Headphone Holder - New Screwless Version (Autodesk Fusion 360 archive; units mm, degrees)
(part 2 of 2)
sketch "Sketch12" plane through (0, -10.6, 0) normal (0, 1, 0) x axis (-1, 0, 0)
  line L1 (27.8828, -27.5) -> (-27.8828, -27.5)
  line L2 (27.8828, 27.5) -> (27.8828, -27.5)
  line L3 (-27.8828, 27.5) -> (27.8828, 27.5)
  line L4 (-27.8828, -27.5) -> (-27.8828, 27.5)
  circle C1 centre (13.4, 0) radius 1.6
  circle C2 centre (-13.4, 0) radius 1.6
  circle C3 centre (13.4, 0) radius 1.25
  circle C4 centre (-13.4, 0) radius 1.25
  concentric C1 C3
  concentric C2 C4
  equal C3 C4
  dimension "d220" diameter C3 = 2.5
extrude "Extrude13" cut sketch "Sketch12" profile of C3 C4 against normal blind 2
copy_paste_bodies "CopyPasteBodies1"
copy_paste_bodies "CopyPasteBodies2"
copy_paste_bodies "CopyPasteBodies3"
delete_face "DeleteFace1"
delete_face "DeleteFace2"
split "Split1" bodies "Peg Left"
copy_paste_bodies "CopyPasteBodies1"
copy_paste_bodies "CopyPasteBodies3"
move "Move1"
combine "Combine1" bodies "Peg Left"
copy_paste_bodies "CutPasteBodies"
sketch "Sketch13" plane through (0, -10.2, 0) normal (0, -1, 0) x axis (1, 0, 0)
  line L1 (-17.4, -27.3) -> (-17.4, 27.3)
  line L2 (17.4, -27.3) -> (-17.4, -27.3)
  line L3 (17.4, 27.3) -> (17.4, -27.3)
  line L4 (-17.4, 27.3) -> (17.4, 27.3)
  line L5 (2.4, 0) -> (-2.4, 0)
  line L6 (-2.6, -7.7) -> (2.6, -7.7)
  line L7 (-2.6, 7.7) -> (-2.6, -7.7)
  line L8 (2.6, 7.7) -> (-2.6, 7.7)
  line L9 (2.6, -7.7) -> (2.6, 7.7)
  line L10 (-2.6, 7.7) -> (2.6, -7.7)
  line L11 (2.6, 7.7) -> (-2.6, -7.7)
  circle C1 centre (-13.4, 0) radius 1.6
  circle C2 centre (13.4, 0) radius 1.6
  arc A1 centre (0, -12.3) radius 2.4 clockwise from (2.4, -12.3) to (-2.4, -12.3)
  arc A2 centre (0, -12.3) radius 2.4 clockwise from (2.4, -12.3) to (-2.4, -12.3)
  arc A3 centre (0, -4.9) radius 2.4 clockwise from (2.4, -4.9) to (-2.4, -4.9)
  arc A4 centre (0, -4.9) radius 2.4 clockwise from (2.4, -4.9) to (-2.4, -4.9)
  point P20 (0, 0)
  point P1 (0, 0)
  point P16 (2.6, -7.7)
  point P17 (-2.6, -7.7)
  point P18 (-2.6, 7.7)
  horizontal L6
  perpendicular L6 L7
  parallel L6 L8
  parallel L7 L9
  coincident L10 P20
  coincident L11 P20
  coincident P1 P20
  dimension "d225" distance P16 P17 = 5.2
  dimension "d226" distance P17 P18 = 15.4
extrude "Extrude1" cut sketch "Sketch13" profile of L6 L7 L8 L9 no distance stored
sketch "Sketch14" plane through (0, -10.2, 0) normal (0, -1, 0) x axis (1, 0, 0)
  line L1 (2.6, -7.7) -> (2.6, 7.7)
  line L2 (-2.6, -7.7) -> (2.6, -7.7)
  line L3 (-2.6, 7.7) -> (-2.6, -7.7)
  line L4 (2.6, 7.7) -> (-2.6, 7.7)
  line L5 (-17.4, -27.3) -> (-17.4, 27.3)
  line L6 (17.4, -27.3) -> (-17.4, -27.3)
  line L7 (17.4, 27.3) -> (17.4, -27.3)
  line L8 (-17.4, 27.3) -> (17.4, 27.3)
  line L9 (-2.6, -12.7) -> (2.6, -12.7)
  line L10 (-2.6, 12.7) -> (-2.6, -12.7)
  line L11 (2.6, 12.7) -> (-2.6, 12.7)
  line L12 (2.6, -12.7) -> (2.6, 12.7)
  line L13 (-2.6, 12.7) -> (2.6, -12.7)
  line L14 (2.6, 12.7) -> (-2.6, -12.7)
  circle C1 centre (-13.4, 0) radius 1.6
  circle C2 centre (13.4, 0) radius 1.6
  point P16 (0, 0)
  point P1 (0, 0)
  horizontal L9
  perpendicular L9 L10
  parallel L9 L11
  parallel L10 L12
  coincident L13 P16
  coincident L14 P16
  coincident P1 P16
  collinear L1 L12
  dimension "d228" distance L2 L9 = 5
extrude "Extrude2" cut sketch "Sketch14" profile of L2 L4 L9 L10 L11 L12 against normal blind 2.5
sketch "Sketch15" plane through (0, -5.4, 0) normal (0, -1, 0) x axis (1, 0, 0)
  line L1 (-2.4, -4.9) -> (-2.4, 0)
  line L2 (2.4, 0) -> (2.4, -4.9)
  line L3 (-2.4, 0) -> (2.4, 0)
  line L4 (-2.6, 7.7) -> (2.6, 7.7)
  line L5 (-2.4, -7.5) -> (2.4, -7.5)
  line L6 (-2.4, 7.5) -> (-2.4, -7.5)
  line L7 (2.4, 7.5) -> (-2.4, 7.5)
  line L8 (2.4, -7.5) -> (2.4, 7.5)
  line L9 (-2.4, 7.5) -> (2.4, -7.5)
  line L10 (2.4, 7.5) -> (-2.4, -7.5)
  arc A1 centre (0, -4.9) radius 2.4 clockwise from (2.4, -4.9) to (-2.4, -4.9)
  point P13 (0, 0)
  point P1 (0, 0)
  horizontal L5
  perpendicular L5 L6
  parallel L5 L7
  parallel L6 L8
  coincident L9 P13
  coincident L10 P13
  coincident P1 P13
  collinear L1 L6
  dimension "d233" distance L4 L7 = 0.2
extrude "Extrude3" add sketch "Sketch15" profile of L1 A1 L2 L3 L5 L6 L7 L8 along normal blind 2.5
sketch "Sketch16" plane through (0, -7.9, 0) normal (0, -1, 0) x axis (1, 0, 0)
  line L1 (-2.4, 7.5) -> (2.4, 7.5)
  line L2 (-2.4, -7.5) -> (-2.4, 7.5)
  line L3 (2.4, -7.5) -> (-2.4, -7.5)
  line L4 (2.4, 7.5) -> (2.4, -7.5)
  line L5 (2.6, -12.7) -> (2.6, 12.7)
  line L6 (-2.6, 12.7) -> (-2.6, -12.7)
  line L7 (2.6, 12.7) -> (-2.6, 12.7)
  line L8 (-2.6, -12.7) -> (2.6, -12.7)
  line L9 (-2.4, -12.5) -> (2.4, -12.5)
  line L10 (-2.4, 12.5) -> (-2.4, -12.5)
  line L11 (2.4, 12.5) -> (-2.4, 12.5)
  line L12 (2.4, -12.5) -> (2.4, 12.5)
  dimension "d236" = 0.2
extrude "Extrude4" add sketch "Sketch16" profile of L1 L2 L3 L4 L9 L10 L11 L12 along normal blind 2.7
move "Move1"
copy_paste_bodies "CopyPasteBodies1"
move "Move1"
work_plane "WorkPlane1"
split "Split1" bodies "Base Plate Body"
move "Move2"
extrude "Extrude1" add of existing geometry to an object bodies "Base Plate"
copy_paste_bodies "CopyPasteBodies1"
move "Move1"
copy_paste_bodies "CopyPasteBodies2"
move "Move2"
copy_paste_bodies "CopyPasteBodies3"
move "Move3"
work_plane "WorkPlane1"
split "Split1" bodies "Lock Plate"
move "Move4"
extrude "Extrude1" add of existing geometry to an object bodies "Lock Plate"
delete_face "DeleteFace1"
delete_face "DeleteFace2"
sketch "Sketch16" plane through (0, 0, 27.5) normal (0, 0, -1) x axis (-1, 0, 0)
  line L1 (-22.6828, -5.4) -> (22.6828, -5.4)
  line L2 (-27.8828, -10.6) -> (-22.6828, -5.4)
  line L3 (27.8828, -10.6) -> (-27.8828, -10.6)
  line L4 (22.6828, -5.4) -> (27.8828, -10.6)
  line L5 (0, -10.6) -> (0, -5.4)
  line L6 (6, -6.4) -> (-6, -6.4)
  line L7 (6, -8.4) -> (6, -6.4)
  line L8 (-6, -8.4) -> (6, -8.4)
  line L9 (-6, -6.4) -> (-6, -8.4)
  point P6 (0, -5.4)
  point P7 (0, -10.6)
  point P10 (6, -8.4)
  point P11 (-6, -8.4)
  point P8 (-6, -6.4)
  midpoint L1 P6
  midpoint L3 P7
  horizontal L6
  vertical L7
  horizontal L8
  vertical L9
  symmetric L5 P10 P11
  dimension "d243" distance P8 P11 = 2
  dimension "d244" distance P10 P11 = 12
  dimension "d245" distance L1 L6 = 1
extrude "Extrude14" cut sketch "Sketch16" profile of L6 L7 L8 L9 against normal blind 1.2
mirror "Mirror1" mirrorStitchTolerance 0.1
delete_face "DeleteFace1"
sketch "Sketch9 (1)" plane through (0, 0, 27.3) normal (0, 0, 1) x axis (1, 0, 0)
  line L1 (-17.4, -10.2) -> (-17.4, -5.4)
  line L2 (17.4, -10.2) -> (-17.4, -10.2)
  line L3 (17.4, -5.4) -> (17.4, -10.2)
  line L4 (-17.4, -5.4) -> (17.4, -5.4)
  line L5 (-6, -8.4) -> (6, -8.4)
  line L6 (-6, -6.4) -> (-6, -8.4)
  line L7 (6, -6.4) -> (-6, -6.4)
  line L8 (6, -8.4) -> (6, -6.4)
  line L9 (-5, -8.2) -> (5, -8.2)
  line L10 (-5, -6.4) -> (-5, -8.2)
  line L11 (5, -6.4) -> (-5, -6.4)
  line L12 (5, -8.2) -> (5, -6.4)
  horizontal L9
  vertical L10
  horizontal L11
  vertical L12
  collinear L7 L11
  dimension "d250" distance L8 L12 = 1
  dimension "d251" distance L6 L10 = 1
  dimension "d252" distance L5 L9 = 0.2
extrude "Extrude12" add sketch "Sketch9 (1)" profile of L9 L10 L11 L12 along normal blind 0.8
chamfer "Chamfer1" distance 1.2 distance 0.8
sketch "Sketch10 (1)" plane through (0, -5.4, 0) normal (0, 1, 0) x axis (-1, 0, 0)
  line L1 (-17.4, -27.3) -> (-17.4, -11.7172)
  line L2 (17.4, -27.3) -> (-17.4, -27.3)
  line L3 (17.4, -11.7172) -> (17.4, -27.3)
  line L4 (22.4, -11.7172) -> (17.4, -11.7172)
  line L5 (22.4, 11.7172) -> (22.4, -11.7172)
  line L6 (17.4, 11.7172) -> (22.4, 11.7172)
  line L7 (17.4, 27.3) -> (17.4, 11.7172)
  line L8 (-17.4, 27.3) -> (17.4, 27.3)
  line L9 (-17.4, 11.7172) -> (-17.4, 27.3)
  line L10 (-22.4, 11.7172) -> (-17.4, 11.7172)
  line L11 (-22.4, -11.7172) -> (-22.4, 11.7172)
  line L12 (-17.4, -11.7172) -> (-22.4, -11.7172)
  line L13 (14.4, 23.3) -> (-14.4, 23.3)
  line L14 (-14.4, 25.3) -> (14.4, 25.3)
  line L15 (14.4, 24.3) -> (-14.4, 24.3)
  line L16 (0, 0) -> (0, 24.3)
  arc A1 centre (14.4, 24.3) radius 1 clockwise from (14.4, 25.3) to (14.4, 23.3)
  arc A2 centre (-14.4, 24.3) radius 1 clockwise from (-14.4, 23.3) to (-14.4, 25.3)
  point P20 (0, 24.3)
  point P21 (0, 24.3)
  point P1 (0, 0)
  point P22 (0, 0)
  tangent L13 A1
  tangent A1 L14
  parallel L13 L14
  tangent L14 A2
  tangent L13 A2
  horizontal L15
  midpoint L15 P20
  coincident P20 P21
  coincident P1 P22
  vertical L16
  dimension "d257" distance L8 L14 = 2
  dimension "d258" distance L9 A2 = 2
  dimension "d259" radius A1 = 1
extrude "Extrude13" cut sketch "Sketch10 (1)" profile of L13 A1 L14 A2 no distance stored
mirror "Mirror3" mirrorStitchTolerance 0.1
sketch "Sketch11 (1)" plane through (0, -5.4, 0) normal (0, 1, 0) x axis (-1, 0, 0)
  line L1 (-14.4, -25.3) -> (14.4, -25.3)
  line L2 (14.4, -23.3) -> (-14.4, -23.3)
  line L3 (14.4, 25.3) -> (-14.4, 25.3)
  line L4 (-14.4, 23.3) -> (14.4, 23.3)
  line L5 (-17.4, -27.3) -> (-17.4, -11.7172)
  line L6 (17.4, -27.3) -> (-17.4, -27.3)
  line L7 (17.4, -11.7172) -> (17.4, -27.3)
  line L8 (22.4, -11.7172) -> (17.4, -11.7172)
  line L9 (22.4, 11.7172) -> (22.4, -11.7172)
  line L10 (17.4, 11.7172) -> (22.4, 11.7172)
  line L11 (17.4, 27.3) -> (17.4, 11.7172)
  line L12 (-17.4, 27.3) -> (17.4, 27.3)
  line L13 (-17.4, 11.7172) -> (-17.4, 27.3)
  line L14 (-22.4, 11.7172) -> (-17.4, 11.7172)
  line L15 (-22.4, -11.7172) -> (-22.4, 11.7172)
  line L16 (-17.4, -11.7172) -> (-22.4, -11.7172)
  line L17 (5, 27.3) -> (5, 28.1)
  line L18 (-5, 28.1) -> (-5, 27.3)
  line L19 (-4, 26.3) -> (4, 26.3)
  arc A1 centre (-14.4, -24.3) radius 1 clockwise from (-14.4, -25.3) to (-14.4, -23.3)
  arc A2 centre (14.4, -24.3) radius 1 clockwise from (14.4, -23.3) to (14.4, -25.3)
  arc A3 centre (14.4, 24.3) radius 1 clockwise from (14.4, 25.3) to (14.4, 23.3)
  arc A4 centre (-14.4, 24.3) radius 1 clockwise from (-14.4, 23.3) to (-14.4, 25.3)
  arc A5 centre (4, 27.3) radius 1 clockwise from (5, 27.3) to (4, 26.3)
  arc A6 centre (-4, 27.3) radius 1 clockwise from (-4, 26.3) to (-5, 27.3)
  point P28 (5, 27.3)
  point P26 (4, 27.3)
  point P30 (-5, 27.3)
  point P29 (-4, 27.3)
  point P33 (5, 27.3)
  point P34 (-5, 27.3)
  coincident L12 P28
  coincident L12 P26
  coincident L12 P30
  coincident L12 P29
  coincident P28 P33
  tangent A5 L19
  tangent A6 L19
  parallel L12 L19
  coincident P30 P34
  dimension "d263" distance L12 L19 = 1
extrude "Extrude14" cut sketch "Sketch11 (1)" profile of L12 A5 A6 L19 against normal blind 1
mirror "Mirror4" mirrorStitchTolerance 0.1
delete_face "DeleteFace3"
sketch "Sketch2" plane through (0, 0, 27.3) normal (0, 0, 1) x axis (1, 0, 0)
  line L1 (-17.4, -10.2) -> (-17.4, -5.4)
  line L2 (17.4, -10.2) -> (-17.4, -10.2)
  line L3 (17.4, -5.4) -> (17.4, -10.2)
  line L4 (-17.4, -5.4) -> (17.4, -5.4)
  line L5 (-6, -8.4) -> (6, -8.4)
  line L6 (-6, -6.4) -> (-6, -8.4)
  line L7 (6, -6.4) -> (-6, -6.4)
  line L8 (6, -8.4) -> (6, -6.4)
  line L9 (-5, -8.2) -> (5, -8.2)
  line L10 (-5, -6.4) -> (-5, -8.2)
  line L11 (5, -6.4) -> (-5, -6.4)
  line L12 (5, -8.2) -> (5, -6.4)
  horizontal L9
  vertical L10
  horizontal L11
  vertical L12
  midpoint L7 L11
  dimension "d269" distance L8 L12 = 1
  dimension "d270" distance L5 L9 = 0.2
extrude "Extrude5" add sketch "Sketch2" profile of L9 L10 L11 L12 along normal blind 0.8
chamfer "Chamfer1" distance 1.2 distance 0.8
mirror "Mirror1" mirrorStitchTolerance 0.1
sketch "Sketch3" plane through (0, -5.4, 0) normal (0, 1, 0) x axis (-1, 0, 0)
  line L1 (-2.6, 7.7) -> (-2.6, -7.7)
  line L2 (2.6, 7.7) -> (-2.6, 7.7)
  line L3 (2.6, -7.7) -> (2.6, 7.7)
  line L4 (-2.6, -7.7) -> (2.6, -7.7)
  line L5 (-17.4, -27.3) -> (-17.4, -11.7172)
  line L6 (17.4, -27.3) -> (-17.4, -27.3)
  line L7 (17.4, -11.7172) -> (17.4, -27.3)
  line L8 (22.4, -11.7172) -> (17.4, -11.7172)
  line L9 (22.4, 11.7172) -> (22.4, -11.7172)
  line L10 (17.4, 11.7172) -> (22.4, 11.7172)
  line L11 (17.4, 27.3) -> (17.4, 11.7172)
  line L12 (-17.4, 27.3) -> (17.4, 27.3)
  line L13 (-17.4, 11.7172) -> (-17.4, 27.3)
  line L14 (-22.4, 11.7172) -> (-17.4, 11.7172)
  line L15 (-22.4, -11.7172) -> (-22.4, 11.7172)
  line L16 (-17.4, -11.7172) -> (-22.4, -11.7172)
  line L17 (4, 26.3) -> (-4, 26.3)
  line L18 (-5, 28.1) -> (-5, 27.3)
  line L19 (5, 28.1) -> (5, 27.3)
  line L20 (14.4, 23.3) -> (-14.4, 23.3)
  line L21 (-14.4, 25.3) -> (14.4, 25.3)
  line L22 (15.4, 24.3) -> (-15.4, 24.3)
  line L23 (0, 25.3) -> (0, 27.3)
  arc A1 centre (-4, 27.3) radius 1 clockwise from (-4, 26.3) to (-5, 27.3)
  arc A2 centre (4, 27.3) radius 1 clockwise from (5, 27.3) to (4, 26.3)
  arc A3 centre (14.4, 24.3) radius 1 clockwise from (14.4, 25.3) to (14.4, 23.3)
  arc A4 centre (-14.4, 24.3) radius 1 clockwise from (-14.4, 23.3) to (-14.4, 25.3)
  point P19 (-5, 27.3)
  point P18 (-4, 27.3)
  point P23 (5, 27.3)
  point P21 (4, 27.3)
  point P24 (-5, 27.3)
  point P26 (5, 27.3)
  point P34 (-15.4, 24.3)
  point P35 (15.4, 24.3)
  point P36 (0, 27.3)
  point P37 (0, 25.3)
  coincident L12 P19
  coincident L12 P18
  coincident L12 P23
  coincident L12 P21
  tangent A1 L17
  tangent A2 L17
  parallel L12 L17
  coincident P19 P24
  coincident P23 P26
  tangent L20 A3
  tangent A3 L21
  parallel L20 L21
  tangent L21 A4
  tangent L20 A4
  midpoint A4 P34
  midpoint A3 P35
  horizontal L22
  midpoint L12 P36
  midpoint L21 P37
  perpendicular L21 L23
  dimension "d275" distance L12 L17 = 1
  dimension "d276" radius A4 = 1
  dimension "d278" distance L12 L21 = 2
  dimension "d279" distance L13 A4 = 2
extrude "Extrude6" cut sketch "Sketch3" profile of L20 A3 L21 A4 no distance stored
extrude "Extrude7" cut sketch "Sketch3" profile of L12 A1 A2 L17 to an object
mirror "Mirror2" mirrorStitchTolerance 0.1
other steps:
base_feature "Base Feature1" bodies "Peg Left", "Single Peg"
base_feature "Base Feature1" bodies "Base Plate"
base_feature "Base Feature1" bodies "Left Pegs"
base_feature "Base Feature2" bodies "Right Pegs"
base_feature "Base Feature3" bodies "Lock Plate"
base_feature "Base Feature3" bodies "Peg Left"
base_feature "Base Feature1" bodies "4 Peg Mount Left Hook", "Left Peg"
base_feature "Base Feature2" bodies "4 Peg Mount Right Hook", "Right Peg"
base_feature "Base Feature3" bodies "4 Peg Mount Middle Part", "Lock Plate"
base_feature "Base Feature4" bodies "Peg Left", "Middle Peg"
create_component "CreateComponent2"
create_component "CreateComponent5"
create_component "CreateComponent8"
remove_body "RemoveBody4"
create_component "CreateComponent9"
create_component "CreateComponent10"
create_component "CreateComponent11"
named bodies: "Base Plate Body", "Part Cutter", "Left Pegs", "Right Pegs", "Lock Plate", "4 Peg Mount Left Hook", "Left Peg", "4 Peg Mount Right Hook", "Right Peg", "4 Peg Mount Middle Part", "Peg Left", "Middle Peg", "Single Peg", "Base Plate"

design "IKEA SKÅDIS"
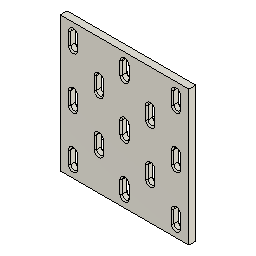
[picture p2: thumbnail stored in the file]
parameter "d27" = 2
parameter "d31" = 8
parameter "d32" = 0
parameter "d34" = 4
parameter "d38" = 0.2
parameter "d39" = 5.4
parameter "d40" = 0
parameter "d41" = 5
parameter "d42" = 0
parameter "d44" = 2.5
parameter "d45" = 15
parameter "d46" = 3
parameter "d47" = 0
parameter "d50" = -40
parameter "d51" = -40
parameter "d52" = 15
parameter "d53" = 15
parameter "d68" = 12
parameter "d69" = 5
parameter "d70" = 67
parameter "d71" = 0
parameter "d72" = 95
parameter "d73" = 0
parameter "d99" = 50
parameter "d101" = 32
parameter "d105" = 4
parameter "d106" = 2
parameter "d108" = 5
parameter "d110" = 134 (= "( 67 * 2 ) * 1 mm")
parameter "d115" = 0
parameter "d116" = 0
parameter "d117" = 4
parameter "d118" = 90
parameter "d119" = 44
parameter "d124" = 40
parameter "d125" = 0
parameter "d127" = 3
parameter "d128" = 2
parameter "d129" = 4
parameter "d130" = 3
parameter "d132" = 75
parameter "d137" = 0
parameter "d138" = 0
parameter "d139" = 45
parameter "d141" = 45
parameter "d142" = 4
parameter "d143" = 25
parameter "d144" = 3
parameter "d145" = 15
parameter "d146" = 30
parameter "d147" = 10
parameter "d148" = -5
parameter "d149" = 0
parameter "d150" = 90
parameter "d151" = 15
parameter "d152" = 0
parameter "d153" = -0.2
parameter "d158" = 0
parameter "d159" = 0
parameter "d160" = -0.2
parameter "d161" = 0
parameter "d162" = -0.2
parameter "d163" = 135
parameter "d164" = 135
parameter "d165" = 24
parameter "d166" = 2.5
parameter "d167" = 0
parameter "d168" = 0.2
parameter "d169" = 0
parameter "d170" = 0
parameter "d171" = 0
parameter "d172" = 0
parameter "d176" = -3
parameter "d177" = 0
parameter "d178" = 2.5
parameter "d179" = -8
parameter "d180" = 0
parameter "d188" = 0
parameter "d189" = 0
parameter "d205" = 3.2
parameter "d206" = 6
parameter "d207" = 0
parameter "d208" = 6
parameter "d209" = -0.4
parameter "d210" = 0
parameter "d211" = -0.2
parameter "d212" = 0
parameter "d214" = 0.1
parameter "d215" = 6.7
parameter "d216" = -25
parameter "d217" = 0
parameter "d218" = 1
sketch "Sketch1" plane through (0, 0, 0) normal (0, 1, 0) x axis (1, 0, 0)
  line L1 (2.6, 4.9) -> (2.6, -4.9)
  line L2 (-2.6, -4.9) -> (-2.6, 4.9)
  line L3 (0, 4.9) -> (0, -4.9)
  line L4 (22.6, -15.1) -> (22.6, -24.9)
  line L5 (17.4, -24.9) -> (17.4, -15.1)
  line L6 (20, -15.1) -> (20, -24.9)
  line L7 (2.6, 0) -> (-2.6, 0)
  line L8 (17.4, 24.9) -> (17.4, 15.1)
  line L9 (22.6, 15.1) -> (22.6, 24.9)
  line L10 (-17.4, -24.9) -> (-17.4, -15.1)
  line L11 (-22.6, -15.1) -> (-22.6, -24.9)
  line L12 (-22.6, 15.1) -> (-22.6, 24.9)
  line L13 (-17.4, 24.9) -> (-17.4, 15.1)
  line L14 (-50, 52.5) -> (50, 52.5)
  line L15 (-50, -52.5) -> (-50, 52.5)
  line L16 (50, -52.5) -> (-50, -52.5)
  line L17 (50, 52.5) -> (50, -52.5)
  line L18 (-50, -52.5) -> (50, 52.5)
  line L19 (50, -52.5) -> (-50, 52.5)
  arc A1 centre (0, 4.9) radius 2.6 clockwise from (-2.6, 4.9) to (2.6, 4.9)
  arc A2 centre (0, -4.9) radius 2.6 clockwise from (2.6, -4.9) to (-2.6, -4.9)
  arc A3 centre (20, -15.1) radius 2.6 clockwise from (17.4, -15.1) to (22.6, -15.1)
  arc A4 centre (20, -24.9) radius 2.6 clockwise from (22.6, -24.9) to (17.4, -24.9)
  arc A5 centre (20, 15.1) radius 2.6 clockwise from (22.6, 15.1) to (17.4, 15.1)
  arc A6 centre (20, 24.9) radius 2.6 clockwise from (17.4, 24.9) to (22.6, 24.9)
  arc A7 centre (-20, -24.9) radius 2.6 clockwise from (-17.4, -24.9) to (-22.6, -24.9)
  arc A8 centre (-20, -15.1) radius 2.6 clockwise from (-22.6, -15.1) to (-17.4, -15.1)
  arc A9 centre (-20, 15.1) radius 2.6 clockwise from (-17.4, 15.1) to (-22.6, 15.1)
  arc A10 centre (-20, 24.9) radius 2.6 clockwise from (-22.6, 24.9) to (-17.4, 24.9)
  point P1 (0, 0)
  point P8 (0, 0)
  point P15 (-2.6, 0)
  point P16 (2.6, 0)
  point P9 (22.6, -24.9)
  point P21 (22.6, 24.9)
  point P10 (22.6, -15.1)
  point P18 (22.6, 15.1)
  point P11 (17.4, -15.1)
  point P19 (17.4, 15.1)
  point P12 (17.4, -24.9)
  point P20 (17.4, 24.9)
  point P26 (-22.6, -24.9)
  point P27 (-22.6, -15.1)
  point P23 (-17.4, -15.1)
  point P24 (-17.4, -24.9)
  point P31 (-22.6, 15.1)
  point P30 (-17.4, 15.1)
  point P33 (-17.4, 24.9)
  point P32 (-22.6, 24.9)
  point P39 (0, 0)
  point P13 (20, -24.9)
  point P25 (-20, -24.9)
  point P35 (50, 52.5)
  point P36 (-50, 52.5)
  point P37 (-50, -52.5)
  tangent L1 A1
  tangent A1 L2
  parallel L1 L2
  tangent L2 A2
  tangent L1 A2
  vertical L3
  coincident P1 P8
  midpoint L3 P8
  tangent L4 A3
  tangent A3 L5
  parallel L4 L5
  tangent L5 A4
  tangent L4 A4
  vertical L6
  equal L2 L5
  equal A2 A4
  midpoint L2 P15
  midpoint L1 P16
  symmetric P9 L7 P21
  symmetric P10 L7 P18
  symmetric P11 L7 P19
  symmetric P12 L7 P20
  symmetric A3 L7 A5
  symmetric A4 L7 A6
  symmetric L3 P9 P26
  symmetric L3 P10 P27
  symmetric L3 P11 P23
  symmetric L3 P12 P24
  symmetric L3 A3 A8
  symmetric L3 A4 A7
  symmetric L3 P18 P31
  symmetric L3 P19 P30
  symmetric L3 A5 A9
  symmetric L3 P20 P33
  symmetric L3 P21 P32
  symmetric L3 A6 A10
  horizontal L14
  perpendicular L14 L15
  parallel L14 L16
  parallel L15 L17
  coincident L18 P39
  coincident L19 P39
  coincident P1 P39
  dimension "d1" = 15
  dimension "d2" distance L1 L2 = 5.2
  dimension "d8" distance P13 P25 = 40
  dimension "d9" distance A3 A5 = 25
  dimension "d16" distance P35 P36 = 100
  dimension "d17" distance P36 P37 = 105
extrude "Extrude1" new body sketch "Sketch1" profile of L1 A1 L2 A2 L4 A3 L5 A4 A5 L8 L9 A6 L10 A7 L11 A8 A9 L12 L13 A10 L14 L15 L16 L17 against normal blind 5.4
fillet "Fillet1" radius 1
rectangular_pattern "R-Pattern1" uSpaceDistance 40 vSpaceDistance 0
rectangular_pattern "R-Pattern2" uSpaceDistance 40 vSpaceDistance 0
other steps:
create_component "CreateComponent1"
